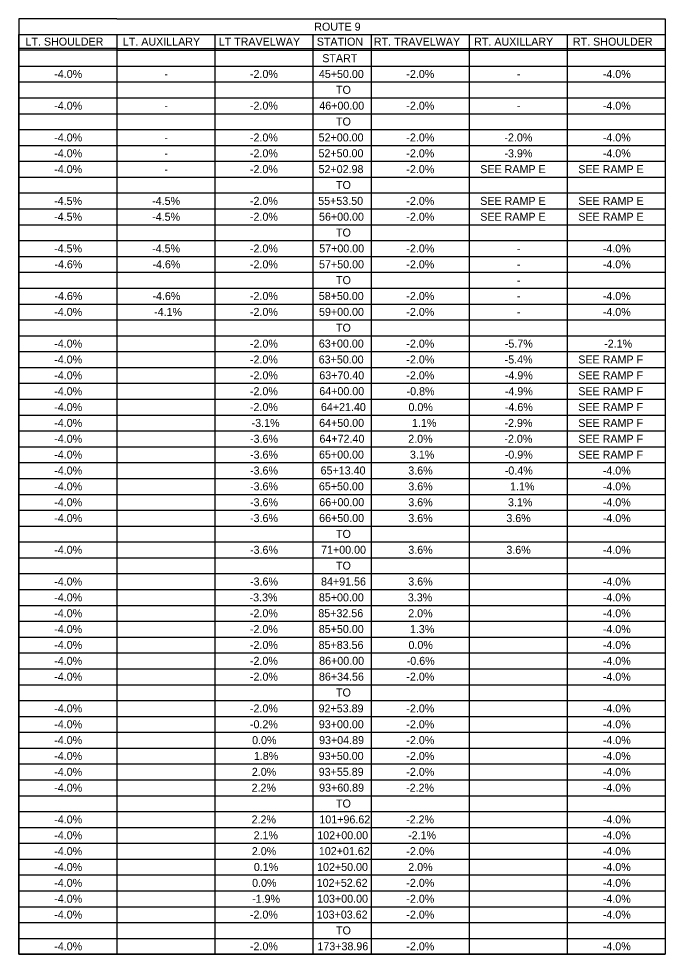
# Model space of a CAD drawing. Extents: x -15319374 to 1762012, y 465773 to 3693661.
# Drawn here: x -15319374.2 to -15319131.7, y 3690637.9 to 3690988.4 of the extents above; entities that cross this region are included whole.
import ezdxf

# ---------------------------------------------------------------- set-up
doc = ezdxf.new("R2010")
doc.units = 0
doc.layers.add('BORDER', color=7, linetype='Continuous')
doc.layers.add('DIMENSIONS', color=7, linetype='Continuous')

msp = doc.modelspace()

# ---------------------------------------------------------------- linework, layer by layer
at = {"layer": 'BORDER'}
for p, q in [((-15319374.17, 3690982.5), (-15319374.17, 3690637.89)), ((-15319337.4, 3690982.5), (-15319337.4, 3690637.89)), ((-15319300.64, 3690982.5), (-15319300.64, 3690637.89)), ((-15319263.87, 3690982.5), (-15319263.87, 3690637.89)), ((-15319241.99, 3690982.5), (-15319241.99, 3690637.89)), ((-15319205.23, 3690982.5), (-15319205.23, 3690637.89)), ((-15319168.46, 3690982.5), (-15319168.46, 3690637.89)), ((-15319131.69, 3690982.5), (-15319131.69, 3690637.89)), ((-15319337.4, 3690977.22), (-15319374.17, 3690977.22)), ((-15319337.4, 3690976.62), (-15319374.17, 3690976.62)), ((-15319374.17, 3690976.62), (-15319374.17, 3690637.89)), ((-15319337.4, 3690977.22), (-15319131.69, 3690977.22)), ((-15319337.4, 3690976.62), (-15319131.69, 3690976.62)), ((-15319374.17, 3690970.68), (-15319131.69, 3690970.68)), ((-15319374.17, 3690970.68), (-15319131.69, 3690970.68)), ((-15319374.17, 3690970.68), (-15319131.69, 3690970.68)), ((-15319374.17, 3690964.74), (-15319131.69, 3690964.74)), ((-15319374.17, 3690958.79), (-15319131.69, 3690958.79)), ((-15319374.17, 3690952.85), (-15319131.69, 3690952.85)), ((-15319374.17, 3690946.91), (-15319131.69, 3690946.91)), ((-15319374.17, 3690940.97), (-15319131.69, 3690940.97)), ((-15319374.17, 3690935.02), (-15319131.69, 3690935.02)), ((-15319374.17, 3690929.08), (-15319131.69, 3690929.08)), ((-15319374.17, 3690923.14), (-15319131.69, 3690923.14)), ((-15319374.17, 3690917.2), (-15319131.69, 3690917.2)), ((-15319374.17, 3690911.25), (-15319131.69, 3690911.25)), ((-15319374.17, 3690905.31), (-15319131.69, 3690905.31)), ((-15319374.17, 3690899.37), (-15319131.69, 3690899.37)), ((-15319374.17, 3690893.43), (-15319131.69, 3690893.43)), ((-15319374.17, 3690887.48), (-15319131.69, 3690887.48)), ((-15319374.17, 3690881.54), (-15319131.69, 3690881.54)), ((-15319374.17, 3690875.6), (-15319131.69, 3690875.6)), ((-15319374.17, 3690869.65), (-15319131.69, 3690869.65)), ((-15319374.17, 3690863.71), (-15319131.69, 3690863.71)), ((-15319374.17, 3690857.77), (-15319131.69, 3690857.77)), ((-15319374.17, 3690851.83), (-15319131.69, 3690851.83)), ((-15319374.17, 3690845.88), (-15319131.69, 3690845.88)), ((-15319374.17, 3690839.94), (-15319131.69, 3690839.94)), ((-15319374.17, 3690834), (-15319131.69, 3690834)), ((-15319374.17, 3690828.06), (-15319131.69, 3690828.06)), ((-15319374.17, 3690822.11), (-15319131.69, 3690822.11)), ((-15319374.17, 3690816.17), (-15319131.69, 3690816.17)), ((-15319374.17, 3690810.23), (-15319131.69, 3690810.23)), ((-15319374.17, 3690804.28), (-15319131.69, 3690804.28)), ((-15319374.17, 3690798.34), (-15319131.69, 3690798.34)), ((-15319374.17, 3690792.4), (-15319131.69, 3690792.4)), ((-15319374.17, 3690786.46), (-15319131.69, 3690786.46)), ((-15319374.17, 3690780.51), (-15319131.69, 3690780.51)), ((-15319374.17, 3690774.57), (-15319131.69, 3690774.57)), ((-15319374.17, 3690768.63), (-15319131.69, 3690768.63)), ((-15319374.17, 3690762.69), (-15319131.69, 3690762.69)), ((-15319374.17, 3690756.74), (-15319131.69, 3690756.74)), ((-15319374.17, 3690750.8), (-15319131.69, 3690750.8)), ((-15319374.17, 3690744.86), (-15319131.69, 3690744.86)), ((-15319374.17, 3690738.91), (-15319131.69, 3690738.91)), ((-15319374.17, 3690732.97), (-15319131.69, 3690732.97)), ((-15319374.17, 3690727.03), (-15319131.69, 3690727.03)), ((-15319374.17, 3690721.09), (-15319131.69, 3690721.09)), ((-15319374.17, 3690715.14), (-15319131.69, 3690715.14)), ((-15319374.17, 3690709.2), (-15319131.69, 3690709.2)), ((-15319374.17, 3690703.26), (-15319131.69, 3690703.26)), ((-15319374.17, 3690697.32), (-15319131.69, 3690697.32)), ((-15319374.17, 3690691.37), (-15319131.69, 3690691.37)), ((-15319374.17, 3690685.43), (-15319131.69, 3690685.43)), ((-15319374.17, 3690679.49), (-15319131.69, 3690679.49)), ((-15319374.17, 3690673.55), (-15319131.69, 3690673.55)), ((-15319374.17, 3690667.6), (-15319131.69, 3690667.6)), ((-15319374.17, 3690661.66), (-15319131.69, 3690661.66)), ((-15319374.17, 3690655.72), (-15319131.69, 3690655.72)), ((-15319374.17, 3690649.77), (-15319131.69, 3690649.77)), ((-15319374.17, 3690643.83), (-15319131.69, 3690643.83)), ((-15319374.17, 3690637.89), (-15319131.69, 3690637.89))]:
    msp.add_line(p, q, dxfattribs=at)
for points in [[(-15319337.4, 3690988.44), (-15319374.17, 3690988.44), (-15319374.17, 3690982.5)], [(-15319337.4, 3690988.44), (-15319168.46, 3690988.44)], [(-15319168.46, 3690988.44), (-15319131.69, 3690988.44), (-15319131.69, 3690982.5)]]:
    msp.add_lwpolyline(points, dxfattribs=at)
msp.add_lwpolyline([(-15319374.17, 3690982.5), (-15319131.69, 3690982.5), (-15319131.69, 3690637.89), (-15319374.17, 3690637.89)], close=True, dxfattribs=at)

# ---------------------------------------------------------------- texts
at = {"layer": 'DIMENSIONS'}
for s, p in [('ROUTE 9', (-15319263.34, 3690983.97)), ('LT. SHOULDER', (-15319371.62, 3690978.36)), ('LT. AUXILLARY', (-15319335.12, 3690978.36)), ('LT TRAVELWAY', (-15319299.18, 3690978.36)), ('STATION', (-15319262.4, 3690978.36)), ('RT. TRAVELWAY', (-15319240.97, 3690978.36)), ('RT. AUXILLARY', (-15319203.37, 3690978.36)), ('RT. SHOULDER', (-15319166.33, 3690978.36)), ('START', (-15319260.33, 3690972.14)), ('-4.0%', (-15319360.84, 3690966.23)), ('-2.0%', (-15319287.45, 3690966.23)), ('45+50.00', (-15319261.6, 3690966.24)), ('-2.0%', (-15319228.8, 3690966.23)), ('-4.0%', (-15319155.12, 3690966.23)), ('-', (-15319319.53, 3690966.23)), ('-', (-15319187.35, 3690966.23)), ('TO', (-15319255.17, 3690960.3)), ('-4.0%', (-15319360.84, 3690954.34)), ('-', (-15319319.53, 3690954.34)), ('-2.0%', (-15319287.45, 3690954.34)), ('46+00.00', (-15319261.45, 3690954.36)), ('-2.0%', (-15319228.8, 3690954.34)), ('-', (-15319187.35, 3690954.34)), ('-4.0%', (-15319155.12, 3690954.34)), ('TO', (-15319255.17, 3690948.41)), ('-4.0%', (-15319360.84, 3690942.45)), ('-', (-15319319.53, 3690942.45)), ('-2.0%', (-15319287.45, 3690942.45)), ('52+00.00', (-15319261.69, 3690942.47)), ('-2.0%', (-15319228.8, 3690942.45)), ('-2.0%', (-15319192.03, 3690942.45)), ('-4.0%', (-15319155.12, 3690942.45)), ('-4.0%', (-15319360.84, 3690936.51)), ('-', (-15319319.53, 3690936.51)), ('-2.0%', (-15319287.45, 3690936.51)), ('52+50.00', (-15319261.74, 3690936.53)), ('-2.0%', (-15319228.8, 3690936.51)), ('-3.9%', (-15319192.01, 3690936.51)), ('-4.0%', (-15319155.12, 3690936.51)), ('-4.0%', (-15319360.84, 3690930.57)), ('-2.0%', (-15319287.45, 3690930.57)), ('52+02.98', (-15319261.73, 3690930.58)), ('-2.0%', (-15319228.8, 3690930.57)), ('SEE RAMP E', (-15319201.09, 3690930.57)), ('SEE RAMP E', (-15319164.32, 3690930.57)), ('-', (-15319319.53, 3690930.57)), ('TO', (-15319255.17, 3690924.64)), ('-4.5%', (-15319360.89, 3690918.68)), ('-4.5%', (-15319324.12, 3690918.68)), ('-2.0%', (-15319287.45, 3690918.68)), ('55+53.50', (-15319261.86, 3690918.7)), ('-2.0%', (-15319228.8, 3690918.68)), ('SEE RAMP E', (-15319201.09, 3690918.68)), ('SEE RAMP E', (-15319164.32, 3690918.68)), ('-4.5%', (-15319360.89, 3690912.74)), ('-4.5%', (-15319324.12, 3690912.74)), ('-2.0%', (-15319287.45, 3690912.74)), ('56+00.00', (-15319261.55, 3690912.76)), ('-2.0%', (-15319228.8, 3690912.74)), ('SEE RAMP E', (-15319201.09, 3690912.74)), ('SEE RAMP E', (-15319164.32, 3690912.74)), ('TO', (-15319255.17, 3690906.81)), ('-4.5%', (-15319360.89, 3690900.86)), ('-4.5%', (-15319324.12, 3690900.86)), ('-2.0%', (-15319287.45, 3690900.86)), ('57+00.00', (-15319261.48, 3690900.87)), ('-2.0%', (-15319228.8, 3690900.86)), ('-', (-15319187.35, 3690900.86)), ('-4.0%', (-15319155.12, 3690900.86)), ('-4.6%', (-15319360.79, 3690894.91)), ('-4.6%', (-15319324.02, 3690894.91)), ('-2.0%', (-15319287.45, 3690894.91)), ('57+50.00', (-15319261.53, 3690894.93)), ('-2.0%', (-15319228.8, 3690894.91)), ('-4.0%', (-15319155.12, 3690894.91)), ('-', (-15319187.35, 3690894.91)), ('TO', (-15319255.17, 3690888.99)), ('-', (-15319187.35, 3690888.97)), ('-4.6%', (-15319360.79, 3690883.03)), ('-4.6%', (-15319324.02, 3690883.03)), ('-2.0%', (-15319287.45, 3690883.03)), ('58+50.00', (-15319261.64, 3690883.04)), ('-2.0%', (-15319228.8, 3690883.03)), ('-', (-15319187.35, 3690883.03)), ('-4.0%', (-15319155.12, 3690883.03)), ('-4.0%', (-15319360.84, 3690877.08)), ('-4.1%', (-15319323.41, 3690877.08)), ('-2.0%', (-15319287.45, 3690877.08)), ('59+00.00', (-15319261.55, 3690877.1)), ('-2.0%', (-15319228.8, 3690877.08)), ('-', (-15319187.35, 3690877.08)), ('-4.0%', (-15319155.12, 3690877.08)), ('TO', (-15319255.17, 3690871.16)), ('-4.0%', (-15319360.84, 3690865.2)), ('-2.0%', (-15319287.45, 3690865.2)), ('63+00.00', (-15319261.62, 3690865.22)), ('-2.0%', (-15319228.8, 3690865.2)), ('-5.7%', (-15319191.87, 3690865.2)), ('-2.1%', (-15319154.61, 3690865.2)), ('-4.0%', (-15319360.84, 3690859.26)), ('-2.0%', (-15319287.45, 3690859.26)), ('63+50.00', (-15319261.67, 3690859.27)), ('-2.0%', (-15319228.8, 3690859.26)), ('-5.4%', (-15319191.94, 3690859.26)), ('SEE RAMP F', (-15319164.32, 3690859.26)), ('-4.0%', (-15319360.84, 3690853.31)), ('-2.0%', (-15319287.45, 3690853.31)), ('63+70.40', (-15319261.45, 3690853.33)), ('-2.0%', (-15319228.8, 3690853.31)), ('-4.9%', (-15319191.85, 3690853.31)), ('SEE RAMP F', (-15319164.32, 3690853.31)), ('-4.0%', (-15319360.84, 3690847.37)), ('-2.0%', (-15319287.45, 3690847.37)), ('64+00.00', (-15319261.45, 3690847.39)), ('-0.8%', (-15319228.71, 3690847.37)), ('-4.9%', (-15319191.85, 3690847.37)), ('SEE RAMP F', (-15319164.32, 3690847.37)), ('-4.0%', (-15319360.84, 3690841.43)), ('-2.0%', (-15319287.45, 3690841.43)), ('64+21.40', (-15319260.84, 3690841.44)), ('0.0%', (-15319228, 3690841.43)), ('-4.6%', (-15319191.85, 3690841.43)), ('SEE RAMP F', (-15319164.32, 3690841.43)), ('-4.0%', (-15319360.84, 3690835.49)), ('-3.1%', (-15319286.81, 3690835.49)), ('64+50.00', (-15319261.5, 3690835.5)), ('1.1%', (-15319226.68, 3690835.49)), ('-2.9%', (-15319191.99, 3690835.49)), ('SEE RAMP F', (-15319164.32, 3690835.49)), ('-4.0%', (-15319360.84, 3690829.54)), ('-3.6%', (-15319287.42, 3690829.54)), ('64+72.40', (-15319261.38, 3690829.56)), ('2.0%', (-15319228.09, 3690829.54)), ('-2.0%', (-15319192.03, 3690829.54)), ('SEE RAMP F', (-15319164.32, 3690829.54)), ('-4.0%', (-15319360.84, 3690823.6)), ('-3.6%', (-15319287.42, 3690823.6)), ('65+00.00', (-15319261.55, 3690823.62)), ('3.1%', (-15319227.46, 3690823.6)), ('-0.9%', (-15319191.89, 3690823.6)), ('SEE RAMP F', (-15319164.32, 3690823.6)), ('-4.0%', (-15319360.84, 3690817.66)), ('-3.6%', (-15319287.42, 3690817.66)), ('65+13.40', (-15319260.96, 3690817.67)), ('3.6%', (-15319228.07, 3690817.66)), ('-0.4%', (-15319191.89, 3690817.66)), ('-4.0%', (-15319155.12, 3690817.66)), ('-4.0%', (-15319360.84, 3690811.71)), ('-3.6%', (-15319287.42, 3690811.71)), ('65+50.00', (-15319261.6, 3690811.73)), ('3.6%', (-15319228.07, 3690811.71)), ('1.1%', (-15319189.91, 3690811.71)), ('-4.0%', (-15319155.12, 3690811.71)), ('-4.0%', (-15319360.84, 3690805.77)), ('-3.6%', (-15319287.42, 3690805.77)), ('66+00.00', (-15319261.45, 3690805.79)), ('3.6%', (-15319228.07, 3690805.77)), ('3.1%', (-15319190.69, 3690805.77)), ('-4.0%', (-15319155.12, 3690805.77)), ('-4.0%', (-15319360.84, 3690799.83)), ('-3.6%', (-15319287.42, 3690799.83)), ('66+50.00', (-15319261.5, 3690799.85)), ('3.6%', (-15319228.07, 3690799.83)), ('3.6%', (-15319191.3, 3690799.83)), ('-4.0%', (-15319155.12, 3690799.83)), ('TO', (-15319255.17, 3690793.9)), ('-4.0%', (-15319360.84, 3690787.94)), ('-3.6%', (-15319287.42, 3690787.94)), ('71+00.00', (-15319260.77, 3690787.96)), ('3.6%', (-15319228.07, 3690787.94)), ('3.6%', (-15319191.3, 3690787.94)), ('-4.0%', (-15319155.12, 3690787.94)), ('TO', (-15319255.17, 3690782.02)), ('-4.0%', (-15319360.84, 3690776.06)), ('-3.6%', (-15319287.42, 3690776.06)), ('84+91.56', (-15319260.79, 3690776.07)), ('3.6%', (-15319228.07, 3690776.06)), ('-4.0%', (-15319155.12, 3690776.06)), ('-4.0%', (-15319360.84, 3690770.12)), ('-3.3%', (-15319287.59, 3690770.12)), ('85+00.00', (-15319261.6, 3690770.13)), ('3.3%', (-15319228.24, 3690770.12)), ('-4.0%', (-15319155.12, 3690770.12)), ('-4.0%', (-15319360.84, 3690764.17)), ('-2.0%', (-15319287.45, 3690764.17)), ('85+32.56', (-15319261.81, 3690764.19)), ('2.0%', (-15319228.09, 3690764.17)), ('-4.0%', (-15319155.12, 3690764.17)), ('-4.0%', (-15319360.84, 3690758.23)), ('-2.0%', (-15319287.45, 3690758.23)), ('85+50.00', (-15319261.64, 3690758.25)), ('1.3%', (-15319227.46, 3690758.23)), ('-4.0%', (-15319155.12, 3690758.23)), ('-4.0%', (-15319360.84, 3690752.29)), ('-2.0%', (-15319287.45, 3690752.29)), ('85+83.56', (-15319261.71, 3690752.3)), ('0.0%', (-15319228, 3690752.29)), ('-4.0%', (-15319155.12, 3690752.29)), ('-4.0%', (-15319360.84, 3690746.34)), ('-2.0%', (-15319287.45, 3690746.34)), ('86+00.00', (-15319261.5, 3690746.36)), ('-0.6%', (-15319228.66, 3690746.34)), ('-4.0%', (-15319155.12, 3690746.34)), ('-4.0%', (-15319360.84, 3690740.4)), ('-2.0%', (-15319287.45, 3690740.4)), ('86+34.56', (-15319261.57, 3690740.42)), ('-2.0%', (-15319228.8, 3690740.4)), ('-4.0%', (-15319155.12, 3690740.4)), ('TO', (-15319255.17, 3690734.48)), ('-4.0%', (-15319360.84, 3690728.52)), ('-2.0%', (-15319287.45, 3690728.52)), ('92+53.89', (-15319261.71, 3690728.53)), ('-2.0%', (-15319228.8, 3690728.52)), ('-4.0%', (-15319155.12, 3690728.52)), ('-4.0%', (-15319360.84, 3690722.57)), ('-0.2%', (-15319287.45, 3690722.57)), ('93+00.00', (-15319261.62, 3690722.59)), ('-2.0%', (-15319228.8, 3690722.57)), ('-4.0%', (-15319155.12, 3690722.57)), ('-4.0%', (-15319360.84, 3690716.63)), ('0.0%', (-15319286.64, 3690716.63)), ('93+04.89', (-15319261.52, 3690716.65)), ('-2.0%', (-15319228.8, 3690716.63)), ('-4.0%', (-15319155.12, 3690716.63)), ('-4.0%', (-15319360.84, 3690710.69)), ('1.8%', (-15319285.98, 3690710.69)), ('93+50.00', (-15319261.67, 3690710.7)), ('-2.0%', (-15319228.8, 3690710.69)), ('-4.0%', (-15319155.12, 3690710.69)), ('-4.0%', (-15319360.84, 3690704.75)), ('2.0%', (-15319286.74, 3690704.75)), ('93+55.89', (-15319261.67, 3690704.76)), ('-2.0%', (-15319228.8, 3690704.75)), ('-4.0%', (-15319155.12, 3690704.75)), ('-4.0%', (-15319360.84, 3690698.8)), ('2.2%', (-15319286.83, 3690698.8)), ('93+60.89', (-15319261.52, 3690698.82)), ('-2.2%', (-15319228.9, 3690698.8)), ('-4.0%', (-15319155.12, 3690698.8)), ('TO', (-15319255.17, 3690692.88)), ('-4.0%', (-15319360.84, 3690686.92)), ('2.2%', (-15319286.83, 3690686.92)), ('101+96.62', (-15319261.42, 3690686.93)), ('-2.2%', (-15319228.9, 3690686.92)), ('-4.0%', (-15319155.12, 3690686.92)), ('-4.0%', (-15319360.84, 3690680.98)), ('2.1%', (-15319286.08, 3690680.98)), ('102+00.00', (-15319262.23, 3690680.99)), ('-2.1%', (-15319228.14, 3690680.98)), ('-4.0%', (-15319155.12, 3690680.98)), ('-4.0%', (-15319360.84, 3690675.03)), ('2.0%', (-15319286.74, 3690675.03)), ('102+01.62', (-15319261.61, 3690675.05)), ('-2.0%', (-15319228.8, 3690675.03)), ('-4.0%', (-15319155.12, 3690675.03)), ('-4.0%', (-15319360.84, 3690669.09)), ('0.1%', (-15319285.98, 3690669.09)), ('102+50.00', (-15319262.28, 3690669.11)), ('2.0%', (-15319228.09, 3690669.09)), ('-4.0%', (-15319155.12, 3690669.09)), ('-4.0%', (-15319360.84, 3690663.15)), ('0.0%', (-15319286.64, 3690663.15)), ('102+52.62', (-15319262.41, 3690663.16)), ('-2.0%', (-15319228.8, 3690663.15)), ('-4.0%', (-15319155.12, 3690663.15)), ('-4.0%', (-15319360.84, 3690657.2)), ('-1.9%', (-15319286.64, 3690657.2)), ('103+00.00', (-15319262.26, 3690657.22)), ('-2.0%', (-15319228.8, 3690657.2)), ('-4.0%', (-15319155.12, 3690657.2)), ('-4.0%', (-15319360.84, 3690651.26)), ('-2.0%', (-15319287.45, 3690651.26)), ('103+03.62', (-15319262.41, 3690651.28)), ('-2.0%', (-15319228.8, 3690651.26)), ('-4.0%', (-15319155.12, 3690651.26)), ('TO', (-15319255.17, 3690645.33)), ('-4.0%', (-15319360.84, 3690639.38)), ('-2.0%', (-15319287.45, 3690639.38)), ('173+38.96', (-15319262.16, 3690639.39)), ('-2.0%', (-15319228.8, 3690639.38)), ('-4.0%', (-15319155.12, 3690639.38))]:
    msp.add_text(s, height=3, dxfattribs=at).set_placement(p)

doc.saveas('drawing.dxf')
